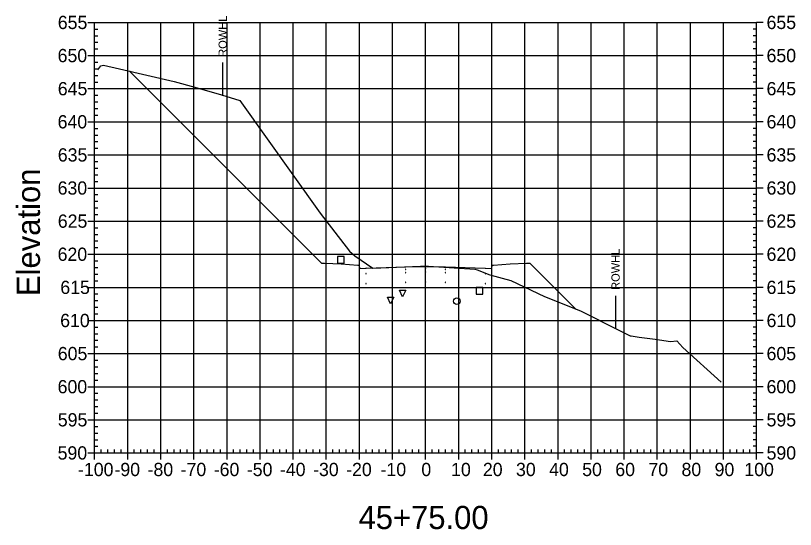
# Model space of a CAD drawing. Extents: x 708103 to 717568, y 374476 to 378707.
# Drawn here: x 711953.1 to 712188.7, y 378251.5 to 378406.7 of the extents above; entities that cross this region are included whole.
import ezdxf

# ---------------------------------------------------------------- set-up
doc = ezdxf.new("R2010")
doc.units = 0
for name, color, linetype in [('1', 7, 'Continuous'), ('10', 7, 'Continuous'), ('13', 7, 'Continuous'), ('14', 7, 'Continuous'), ('22', 7, 'Continuous'), ('4', 7, 'Continuous'), ('57', 7, 'Continuous'), ('60', 7, 'Continuous'), ('Existing', 7, 'Continuous'), ('XS_Right_of_Way', 7, 'Continuous')]:
    doc.layers.add(name, color=color, linetype=linetype)

msp = doc.modelspace()

# ---------------------------------------------------------------- linework, layer by layer
for points in [[(712058.93, 378328.7), (712059.03, 378328.7), (712059.03, 378328.8), (712058.93, 378328.8)], [(712070.93, 378330.06), (712071.03, 378330.06), (712071.03, 378330.16), (712070.93, 378330.16)], [(712070.93, 378329.06), (712071.03, 378329.06), (712071.03, 378329.16), (712070.93, 378329.16)], [(712076.93, 378330.18), (712077.03, 378330.18), (712077.03, 378330.28), (712076.93, 378330.28)], [(712076.93, 378329.18), (712077.03, 378329.18), (712077.03, 378329.28), (712076.93, 378329.28)], [(712082.93, 378330.06), (712083.03, 378330.06), (712083.03, 378330.16), (712082.93, 378330.16)], [(712082.93, 378329.06), (712083.03, 378329.06), (712083.03, 378329.16), (712082.93, 378329.16)], [(712094.93, 378328.7), (712095.03, 378328.7), (712095.03, 378328.8), (712094.93, 378328.8)], [(712076.93, 378326.18), (712077.03, 378326.18), (712077.03, 378326.28), (712076.93, 378326.28)], [(712058.93, 378325.7), (712059.03, 378325.7), (712059.03, 378325.8), (712058.93, 378325.8)], [(712070.93, 378326.06), (712071.03, 378326.06), (712071.03, 378326.16), (712070.93, 378326.16)], [(712082.93, 378326.06), (712083.03, 378326.06), (712083.03, 378326.16), (712082.93, 378326.16)], [(712094.93, 378325.7), (712095.03, 378325.7), (712095.03, 378325.8), (712094.93, 378325.8)]]:
    msp.add_lwpolyline(points, close=True)
at = {"layer": '1'}
for points in [[(712066.42, 378319.64), (712065.42, 378321.64), (712067.42, 378321.64)], [(712070.05, 378321.8), (712069.05, 378323.8), (712071.05, 378323.8)]]:
    msp.add_lwpolyline(points, close=True, dxfattribs=at)
at = {"layer": '10'}
msp.add_lwpolyline([(712050.35, 378331.98), (712052.35, 378331.98), (712052.35, 378333.98), (712050.35, 378333.98)], close=True, dxfattribs=at)
at = {"layer": '13'}
msp.add_circle((712086.43, 378320.46), 1, dxfattribs=at)
at = {"layer": '14'}
for points in [[(711987.53, 378389.93), (711987.53, 378389.98), (711987.53, 378389.93), (711987.48, 378389.93), (711987.53, 378389.93), (711987.53, 378389.88), (711987.53, 378389.93), (711987.58, 378389.93)], [(712058.98, 378330.42), (712058.98, 378330.47), (712058.98, 378330.42), (712058.93, 378330.42), (712058.98, 378330.42), (712058.98, 378330.37), (712058.98, 378330.42), (712059.03, 378330.42)], [(712076.98, 378330.9), (712076.98, 378330.95), (712076.98, 378330.9), (712076.93, 378330.9), (712076.98, 378330.9), (712076.98, 378330.85), (712076.98, 378330.9), (712077.03, 378330.9)], [(712094.98, 378330.42), (712094.98, 378330.47), (712094.98, 378330.42), (712094.93, 378330.42), (712094.98, 378330.42), (712094.98, 378330.37), (712094.98, 378330.42), (712095.03, 378330.42)], [(712122.38, 378318.08), (712122.38, 378318.13), (712122.38, 378318.08), (712122.33, 378318.08), (712122.38, 378318.08), (712122.38, 378318.03), (712122.38, 378318.08), (712122.43, 378318.08)]]:
    msp.add_lwpolyline(points, dxfattribs=at)
at = {"layer": '22'}
msp.add_lwpolyline([(711987.53, 378389.93), (712045.48, 378331.98), (712046.48, 378331.94), (712051.48, 378331.74), (712056.48, 378331.34), (712056.9, 378331.34), (712056.98, 378330.34), (712058.98, 378330.42), (712070.98, 378330.78), (712076.98, 378330.9), (712082.98, 378330.78), (712094.98, 378330.42), (712096.98, 378330.34), (712097.07, 378331.34), (712097.48, 378331.34), (712102.48, 378331.74), (712107.48, 378331.94), (712108.48, 378331.98), (712122.38, 378318.08)], dxfattribs=at)
at = {"layer": '4'}
msp.add_lwpolyline([(712092.23, 378322.62), (712094.23, 378322.62), (712094.23, 378324.62), (712092.23, 378324.62)], close=True, dxfattribs=at)
at = {"layer": '57'}
for p, q in [((711974.98, 378404.63), (711976.98, 378404.63)), ((711976.98, 378404.63), (712176.98, 378404.63)), ((711976.98, 378274.63), (711976.98, 378404.63)), ((711976.98, 378274.63), (711976.98, 378404.63)), ((711986.98, 378274.63), (711986.98, 378404.63)), ((711996.98, 378274.63), (711996.98, 378404.63)), ((712006.98, 378274.63), (712006.98, 378404.63)), ((712016.98, 378274.63), (712016.98, 378404.63)), ((712026.98, 378274.63), (712026.98, 378404.63)), ((712036.98, 378274.63), (712036.98, 378404.63)), ((712046.98, 378274.63), (712046.98, 378404.63)), ((712056.98, 378274.63), (712056.98, 378404.63)), ((712066.98, 378274.63), (712066.98, 378404.63)), ((712076.98, 378274.63), (712076.98, 378404.63)), ((712086.98, 378274.63), (712086.98, 378404.63)), ((712096.98, 378274.63), (712096.98, 378404.63)), ((712106.98, 378274.63), (712106.98, 378404.63)), ((712116.98, 378274.63), (712116.98, 378404.63)), ((712126.98, 378274.63), (712126.98, 378404.63)), ((712136.98, 378274.63), (712136.98, 378404.63)), ((712146.98, 378274.63), (712146.98, 378404.63)), ((712156.98, 378274.63), (712156.98, 378404.63)), ((712166.98, 378274.63), (712166.98, 378404.63)), ((712176.98, 378274.63), (712176.98, 378404.63)), ((712176.98, 378274.63), (712176.98, 378404.63)), ((712178.98, 378404.63), (712176.98, 378404.63)), ((711976.98, 378402.63), (711977.98, 378402.63)), ((712176.98, 378402.63), (712175.98, 378402.63)), ((711976.98, 378400.63), (711977.98, 378400.63)), ((712176.98, 378400.63), (712175.98, 378400.63)), ((711976.98, 378398.63), (711977.98, 378398.63)), ((712176.98, 378398.63), (712175.98, 378398.63)), ((711974.98, 378394.63), (711976.98, 378394.63)), ((711976.98, 378396.63), (711977.98, 378396.63)), ((711976.98, 378394.63), (712176.98, 378394.63)), ((712176.98, 378396.63), (712175.98, 378396.63)), ((712178.98, 378394.63), (712176.98, 378394.63)), ((711976.98, 378392.63), (711977.98, 378392.63)), ((712176.98, 378392.63), (712175.98, 378392.63)), ((711976.98, 378390.63), (711977.98, 378390.63)), ((712176.98, 378390.63), (712175.98, 378390.63)), ((711976.98, 378388.63), (711977.98, 378388.63)), ((712176.98, 378388.63), (712175.98, 378388.63)), ((711976.98, 378386.63), (711977.98, 378386.63)), ((712176.98, 378386.63), (712175.98, 378386.63)), ((711974.98, 378384.63), (711976.98, 378384.63)), ((711976.98, 378384.63), (712176.98, 378384.63)), ((712178.98, 378384.63), (712176.98, 378384.63)), ((711976.98, 378382.63), (711977.98, 378382.63)), ((711976.98, 378380.63), (711977.98, 378380.63)), ((712176.98, 378382.63), (712175.98, 378382.63)), ((712176.98, 378380.63), (712175.98, 378380.63)), ((711976.98, 378378.63), (711977.98, 378378.63)), ((712176.98, 378378.63), (712175.98, 378378.63)), ((711976.98, 378376.63), (711977.98, 378376.63)), ((712176.98, 378376.63), (712175.98, 378376.63)), ((711974.98, 378374.63), (711976.98, 378374.63)), ((711976.98, 378374.63), (712176.98, 378374.63)), ((712178.98, 378374.63), (712176.98, 378374.63)), ((711976.98, 378372.63), (711977.98, 378372.63)), ((712176.98, 378372.63), (712175.98, 378372.63)), ((711976.98, 378370.63), (711977.98, 378370.63)), ((712176.98, 378370.63), (712175.98, 378370.63)), ((711976.98, 378368.63), (711977.98, 378368.63)), ((711976.98, 378366.63), (711977.98, 378366.63)), ((712176.98, 378368.63), (712175.98, 378368.63)), ((712176.98, 378366.63), (712175.98, 378366.63)), ((711974.98, 378364.63), (711976.98, 378364.63)), ((711976.98, 378364.63), (712176.98, 378364.63)), ((712178.98, 378364.63), (712176.98, 378364.63)), ((711976.98, 378362.63), (711977.98, 378362.63)), ((712176.98, 378362.63), (712175.98, 378362.63)), ((711976.98, 378360.63), (711977.98, 378360.63)), ((712176.98, 378360.63), (712175.98, 378360.63)), ((711976.98, 378358.63), (711977.98, 378358.63)), ((712176.98, 378358.63), (712175.98, 378358.63)), ((711974.98, 378354.63), (711976.98, 378354.63)), ((711976.98, 378356.63), (711977.98, 378356.63)), ((711976.98, 378354.63), (712176.98, 378354.63)), ((712176.98, 378356.63), (712175.98, 378356.63)), ((712178.98, 378354.63), (712176.98, 378354.63)), ((711976.98, 378352.63), (711977.98, 378352.63)), ((712176.98, 378352.63), (712175.98, 378352.63)), ((711976.98, 378350.63), (711977.98, 378350.63)), ((712176.98, 378350.63), (712175.98, 378350.63)), ((711976.98, 378348.63), (711977.98, 378348.63)), ((712176.98, 378348.63), (712175.98, 378348.63)), ((711976.98, 378346.63), (711977.98, 378346.63)), ((712176.98, 378346.63), (712175.98, 378346.63)), ((711974.98, 378344.63), (711976.98, 378344.63)), ((711976.98, 378344.63), (712176.98, 378344.63)), ((712178.98, 378344.63), (712176.98, 378344.63)), ((711976.98, 378342.63), (711977.98, 378342.63)), ((711976.98, 378340.63), (711977.98, 378340.63)), ((712176.98, 378342.63), (712175.98, 378342.63)), ((712176.98, 378340.63), (712175.98, 378340.63)), ((711976.98, 378338.63), (711977.98, 378338.63)), ((712176.98, 378338.63), (712175.98, 378338.63)), ((711976.98, 378336.63), (711977.98, 378336.63)), ((712176.98, 378336.63), (712175.98, 378336.63)), ((711974.98, 378334.63), (711976.98, 378334.63)), ((711976.98, 378334.63), (712176.98, 378334.63)), ((712178.98, 378334.63), (712176.98, 378334.63)), ((711976.98, 378332.63), (711977.98, 378332.63)), ((712176.98, 378332.63), (712175.98, 378332.63)), ((711976.98, 378330.63), (711977.98, 378330.63)), ((711976.98, 378328.63), (711977.98, 378328.63)), ((712176.98, 378330.63), (712175.98, 378330.63)), ((712176.98, 378328.63), (712175.98, 378328.63)), ((711976.98, 378326.63), (711977.98, 378326.63)), ((712176.98, 378326.63), (712175.98, 378326.63)), ((711974.98, 378324.63), (711976.98, 378324.63)), ((711976.98, 378324.63), (712176.98, 378324.63)), ((712178.98, 378324.63), (712176.98, 378324.63)), ((711976.98, 378322.63), (711977.98, 378322.63)), ((712176.98, 378322.63), (712175.98, 378322.63)), ((711976.98, 378320.63), (711977.98, 378320.63)), ((712176.98, 378320.63), (712175.98, 378320.63)), ((711976.98, 378318.63), (711977.98, 378318.63)), ((712176.98, 378318.63), (712175.98, 378318.63)), ((711974.98, 378314.63), (711976.98, 378314.63)), ((711976.98, 378316.63), (711977.98, 378316.63)), ((711976.98, 378314.63), (712176.98, 378314.63)), ((712176.98, 378316.63), (712175.98, 378316.63)), ((712178.98, 378314.63), (712176.98, 378314.63)), ((711976.98, 378312.63), (711977.98, 378312.63)), ((712176.98, 378312.63), (712175.98, 378312.63)), ((711976.98, 378310.63), (711977.98, 378310.63)), ((712176.98, 378310.63), (712175.98, 378310.63)), ((711976.98, 378308.63), (711977.98, 378308.63)), ((712176.98, 378308.63), (712175.98, 378308.63)), ((711976.98, 378306.63), (711977.98, 378306.63)), ((712176.98, 378306.63), (712175.98, 378306.63)), ((711974.98, 378304.63), (711976.98, 378304.63)), ((711976.98, 378304.63), (712176.98, 378304.63)), ((712178.98, 378304.63), (712176.98, 378304.63)), ((711976.98, 378302.63), (711977.98, 378302.63)), ((711976.98, 378300.63), (711977.98, 378300.63)), ((712176.98, 378302.63), (712175.98, 378302.63)), ((712176.98, 378300.63), (712175.98, 378300.63)), ((711976.98, 378298.63), (711977.98, 378298.63)), ((712176.98, 378298.63), (712175.98, 378298.63)), ((711976.98, 378296.63), (711977.98, 378296.63)), ((712176.98, 378296.63), (712175.98, 378296.63)), ((711974.98, 378294.63), (711976.98, 378294.63)), ((711976.98, 378294.63), (712176.98, 378294.63)), ((712178.98, 378294.63), (712176.98, 378294.63)), ((711976.98, 378292.63), (711977.98, 378292.63)), ((712176.98, 378292.63), (712175.98, 378292.63)), ((711976.98, 378290.63), (711977.98, 378290.63)), ((711976.98, 378288.63), (711977.98, 378288.63)), ((712176.98, 378290.63), (712175.98, 378290.63)), ((712176.98, 378288.63), (712175.98, 378288.63)), ((711976.98, 378286.63), (711977.98, 378286.63)), ((712176.98, 378286.63), (712175.98, 378286.63)), ((711974.98, 378284.63), (711976.98, 378284.63)), ((711976.98, 378284.63), (712176.98, 378284.63)), ((712178.98, 378284.63), (712176.98, 378284.63)), ((711976.98, 378282.63), (711977.98, 378282.63)), ((712176.98, 378282.63), (712175.98, 378282.63)), ((711976.98, 378280.63), (711977.98, 378280.63)), ((712176.98, 378280.63), (712175.98, 378280.63)), ((711976.98, 378278.63), (711977.98, 378278.63)), ((712176.98, 378278.63), (712175.98, 378278.63)), ((711974.98, 378274.63), (711976.98, 378274.63)), ((711976.98, 378276.63), (711977.98, 378276.63)), ((711976.98, 378274.63), (712176.98, 378274.63)), ((711976.98, 378274.63), (712176.98, 378274.63)), ((711976.98, 378272.63), (711976.98, 378274.63)), ((711978.98, 378274.63), (711978.98, 378275.63)), ((711980.98, 378274.63), (711980.98, 378275.63)), ((711982.98, 378274.63), (711982.98, 378275.63)), ((711984.98, 378274.63), (711984.98, 378275.63)), ((711986.98, 378272.63), (711986.98, 378274.63)), ((711988.98, 378274.63), (711988.98, 378275.63)), ((711990.98, 378274.63), (711990.98, 378275.63)), ((711992.98, 378274.63), (711992.98, 378275.63)), ((711994.98, 378274.63), (711994.98, 378275.63)), ((711996.98, 378272.63), (711996.98, 378274.63)), ((711998.98, 378274.63), (711998.98, 378275.63)), ((712000.98, 378274.63), (712000.98, 378275.63)), ((712002.98, 378274.63), (712002.98, 378275.63)), ((712004.98, 378274.63), (712004.98, 378275.63)), ((712006.98, 378272.63), (712006.98, 378274.63)), ((712008.98, 378274.63), (712008.98, 378275.63)), ((712010.98, 378274.63), (712010.98, 378275.63)), ((712012.98, 378274.63), (712012.98, 378275.63)), ((712014.98, 378274.63), (712014.98, 378275.63)), ((712016.98, 378272.63), (712016.98, 378274.63)), ((712018.98, 378274.63), (712018.98, 378275.63)), ((712020.98, 378274.63), (712020.98, 378275.63)), ((712022.98, 378274.63), (712022.98, 378275.63)), ((712024.98, 378274.63), (712024.98, 378275.63)), ((712026.98, 378272.63), (712026.98, 378274.63)), ((712028.98, 378274.63), (712028.98, 378275.63)), ((712030.98, 378274.63), (712030.98, 378275.63)), ((712032.98, 378274.63), (712032.98, 378275.63)), ((712034.98, 378274.63), (712034.98, 378275.63)), ((712036.98, 378272.63), (712036.98, 378274.63)), ((712038.98, 378274.63), (712038.98, 378275.63)), ((712040.98, 378274.63), (712040.98, 378275.63)), ((712042.98, 378274.63), (712042.98, 378275.63)), ((712044.98, 378274.63), (712044.98, 378275.63)), ((712046.98, 378272.63), (712046.98, 378274.63)), ((712048.98, 378274.63), (712048.98, 378275.63)), ((712050.98, 378274.63), (712050.98, 378275.63)), ((712052.98, 378274.63), (712052.98, 378275.63)), ((712054.98, 378274.63), (712054.98, 378275.63)), ((712056.98, 378272.63), (712056.98, 378274.63)), ((712058.98, 378274.63), (712058.98, 378275.63)), ((712060.98, 378274.63), (712060.98, 378275.63)), ((712062.98, 378274.63), (712062.98, 378275.63)), ((712064.98, 378274.63), (712064.98, 378275.63)), ((712066.98, 378272.63), (712066.98, 378274.63)), ((712068.98, 378274.63), (712068.98, 378275.63)), ((712070.98, 378274.63), (712070.98, 378275.63)), ((712072.98, 378274.63), (712072.98, 378275.63)), ((712074.98, 378274.63), (712074.98, 378275.63)), ((712076.98, 378272.63), (712076.98, 378274.63)), ((712078.98, 378274.63), (712078.98, 378275.63)), ((712080.98, 378274.63), (712080.98, 378275.63)), ((712082.98, 378274.63), (712082.98, 378275.63)), ((712084.98, 378274.63), (712084.98, 378275.63)), ((712086.98, 378272.63), (712086.98, 378274.63)), ((712088.98, 378274.63), (712088.98, 378275.63)), ((712090.98, 378274.63), (712090.98, 378275.63)), ((712092.98, 378274.63), (712092.98, 378275.63)), ((712094.98, 378274.63), (712094.98, 378275.63)), ((712096.98, 378272.63), (712096.98, 378274.63)), ((712098.98, 378274.63), (712098.98, 378275.63)), ((712100.98, 378274.63), (712100.98, 378275.63)), ((712102.98, 378274.63), (712102.98, 378275.63)), ((712104.98, 378274.63), (712104.98, 378275.63)), ((712106.98, 378272.63), (712106.98, 378274.63)), ((712108.98, 378274.63), (712108.98, 378275.63)), ((712110.98, 378274.63), (712110.98, 378275.63)), ((712112.98, 378274.63), (712112.98, 378275.63)), ((712114.98, 378274.63), (712114.98, 378275.63)), ((712116.98, 378272.63), (712116.98, 378274.63)), ((712118.98, 378274.63), (712118.98, 378275.63)), ((712120.98, 378274.63), (712120.98, 378275.63)), ((712122.98, 378274.63), (712122.98, 378275.63)), ((712124.98, 378274.63), (712124.98, 378275.63)), ((712126.98, 378272.63), (712126.98, 378274.63)), ((712128.98, 378274.63), (712128.98, 378275.63)), ((712130.98, 378274.63), (712130.98, 378275.63)), ((712132.98, 378274.63), (712132.98, 378275.63)), ((712134.98, 378274.63), (712134.98, 378275.63)), ((712136.98, 378272.63), (712136.98, 378274.63)), ((712138.98, 378274.63), (712138.98, 378275.63)), ((712140.98, 378274.63), (712140.98, 378275.63)), ((712142.98, 378274.63), (712142.98, 378275.63)), ((712144.98, 378274.63), (712144.98, 378275.63)), ((712146.98, 378272.63), (712146.98, 378274.63)), ((712148.98, 378274.63), (712148.98, 378275.63)), ((712150.98, 378274.63), (712150.98, 378275.63)), ((712152.98, 378274.63), (712152.98, 378275.63)), ((712154.98, 378274.63), (712154.98, 378275.63)), ((712156.98, 378272.63), (712156.98, 378274.63)), ((712158.98, 378274.63), (712158.98, 378275.63)), ((712160.98, 378274.63), (712160.98, 378275.63)), ((712162.98, 378274.63), (712162.98, 378275.63)), ((712164.98, 378274.63), (712164.98, 378275.63)), ((712166.98, 378272.63), (712166.98, 378274.63)), ((712168.98, 378274.63), (712168.98, 378275.63)), ((712170.98, 378274.63), (712170.98, 378275.63)), ((712172.98, 378274.63), (712172.98, 378275.63)), ((712174.98, 378274.63), (712174.98, 378275.63)), ((712176.98, 378276.63), (712175.98, 378276.63)), ((712176.98, 378272.63), (712176.98, 378274.63)), ((712178.98, 378274.63), (712176.98, 378274.63))]:
    msp.add_line(p, q, dxfattribs=at)
at = {"layer": 'Existing'}
msp.add_lwpolyline([(711977.94, 378390.27), (711978.82, 378391.5), (711979.66, 378391.73), (711984.47, 378390.65), (712001.04, 378386.76), (712007.27, 378385.13), (712015.33, 378382.72), (712020.83, 378381.09), (712045.1, 378347.07), (712054, 378335.55), (712055.56, 378334.14), (712061.07, 378330.4), (712075.42, 378331.04), (712076.83, 378331.07), (712077.84, 378330.99), (712091.88, 378330.13), (712092.51, 378329.9), (712096.39, 378328.38), (712102.77, 378326.68), (712112.88, 378321.89), (712123.74, 378317.54), (712135.38, 378311.7), (712138.8, 378310.01), (712139.13, 378309.95), (712141.49, 378309.54), (712146.31, 378309), (712150.97, 378308.28), (712152.87, 378308.45), (712154.68, 378306.43), (712166.3, 378295.96)], dxfattribs=at)
at = {"layer": 'XS_Right_of_Way'}
for p, q in [((712015.62, 378392.49), (712015.62, 378382.49)), ((712134.3, 378322.11), (712134.3, 378312.11))]:
    msp.add_line(p, q, dxfattribs=at)

# ---------------------------------------------------------------- texts
at = {"layer": '1'}
msp.add_text('45+75.00', height=7, dxfattribs=at).set_placement((712056.71, 378251.63))
at = {"layer": '14'}
for p in [(712046.45, 378331.89), (712046.45, 378331.22), (712051.45, 378331.02), (712102.45, 378331.02), (712107.45, 378331.89), (712107.45, 378331.22)]:
    msp.add_text('+', height=0.1, dxfattribs=at).set_placement(p)
at = {"layer": '57'}
for s, p in [('655', (711965.86, 378402.63)), ('655', (712179.98, 378402.63)), ('650', (711965.81, 378392.63)), ('650', (712179.98, 378392.63)), ('645', (711965.86, 378382.63)), ('645', (712179.98, 378382.63)), ('640', (711965.81, 378372.63)), ('640', (712179.98, 378372.63)), ('635', (711965.86, 378362.63)), ('635', (712179.98, 378362.63)), ('630', (711965.81, 378352.63)), ('630', (712179.98, 378352.63)), ('625', (711965.86, 378342.63)), ('625', (712179.98, 378342.63)), ('620', (711965.81, 378332.63)), ('620', (712179.98, 378332.63)), ('615', (711966.63, 378322.63)), ('615', (712179.98, 378322.63)), ('610', (711966.58, 378312.63)), ('610', (712179.98, 378312.63)), ('605', (711965.86, 378302.63)), ('605', (712179.98, 378302.63)), ('600', (711965.81, 378292.63)), ('600', (712179.98, 378292.63)), ('595', (711965.86, 378282.63)), ('595', (712179.98, 378282.63)), ('590', (711965.81, 378272.63)), ('590', (712179.98, 378272.63)), ('-100', (711971.97, 378267.63)), ('-90', (711982.98, 378267.63)), ('-80', (711992.98, 378267.63)), ('-70', (712002.98, 378267.63)), ('-60', (712012.98, 378267.63)), ('-50', (712022.98, 378267.63)), ('-40', (712032.98, 378267.63)), ('-30', (712042.98, 378267.63)), ('-20', (712052.98, 378267.63)), ('-10', (712063.37, 378267.63)), ('0', (712075.69, 378267.63)), ('10', (712084.68, 378267.63)), ('20', (712094.29, 378267.63)), ('30', (712104.29, 378267.63)), ('40', (712114.29, 378267.63)), ('50', (712124.29, 378267.63)), ('60', (712134.29, 378267.63)), ('70', (712144.29, 378267.63)), ('80', (712154.29, 378267.63)), ('90', (712164.29, 378267.63)), ('100', (712173.28, 378267.63))]:
    msp.add_text(s, height=4, dxfattribs=at).set_placement(p)
at = {"layer": '60'}
msp.add_text('Elevation', height=7, rotation=90, dxfattribs=at).set_placement((711960.48, 378321.99))
at = {"layer": 'XS_Right_of_Way'}
for p in [(712016.94, 378394.25), (712135.62, 378323.87)]:
    msp.add_text('ROWHL', height=2.5, rotation=90, dxfattribs=at).set_placement(p)

doc.saveas('drawing.dxf')
